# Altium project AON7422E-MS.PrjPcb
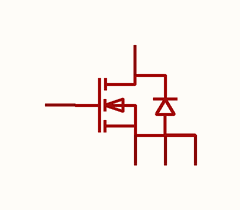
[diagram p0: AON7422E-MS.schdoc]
1 sheet, 1 parts. Net scope: global (net labels, ports and power ports of the same name join across sheets).

## Sheet AON7422E-MS.schdoc
size 127 x 101 mm

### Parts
Q?  aon7422e-ms  [POWERDI3333-8_DMN7022LFGQ-7]  (value not drawn)

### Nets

Not connected (* = marked no-connect by the designer): Q? 1(S) 2(S) 3(S) 4(G) 5(D)

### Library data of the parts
Q? = aon7422e-ms: 数量:1个N沟道;漏源电压(Vdss):30V;连续漏极电流(Id):80A;导通电阻(RDS(on)):6mΩ@10V;耗散功率(Pd):62.5W;阈值电压(Vgs(th)):2.5V;; Manufacturer: MSKSEMI(美森科); AddInBom: yes; ModelId: 296e462280334ba794f41fc0f4558c2c; ModelTransform: 130.708,130.708,0,0,0,0,0,18.625,0; Number: 1个N沟道; Drain to Source Voltage: 30V; Current - Continuous Drain(Id): 80A; Pd - Power Dissipation: 62.5W; Gate Threshold Voltage (Vgs(th)): 2.5V; Gate Charge(Qg): 31.6nC@4.5V; Input Capacitance(Ciss): 4nF; Type: N沟道; Output Capacitance(Coss): 530pF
